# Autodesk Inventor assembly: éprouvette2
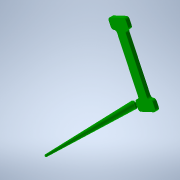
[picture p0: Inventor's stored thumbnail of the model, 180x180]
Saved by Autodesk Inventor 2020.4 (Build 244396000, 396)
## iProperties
Created: 2021-10
Part Number: éprouvette2
Document SubType Name: Assembly
Designer: mel
Author: mel
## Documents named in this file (6)
- D:\travail\année 2020-2021\itec\prépa injection plastique eduscol\dossier de travail\Ensemble des pièces de l'activité\Conception de moule1\éprouvette2.iam
- D:\travail\année 2020-2021\itec\prépa injection plastique eduscol\dossier de travail\Ensemble des pièces de l'activité\Conception de moule1\éprouvette2_éprouvette_LY.iam
- D:\travail\année 2020-2021\itec\prépa injection plastique eduscol\dossier de travail\Ensemble des pièces de l'activité\Conception de moule1\éprouvette2_RG.ipt
- D:\travail\année 2020-2021\itec\prépa injection plastique eduscol\dossier de travail\Ensemble des pièces de l'activité\Conception de moule1\Mo\FUTABA_SA-S 2\éprouvette2_MB.iam
- D:\travail\année 2020-2021\itec\prépa injection plastique eduscol\dossier de travail\Ensemble des pièces de l'activité\Conception de moule1\Buse d'injection\HASCO_Z51\éprouvette2_Z51-18x76-3,5.ipt
- D:\travail\année 2020-2021\itec\prépa injection plastique eduscol\dossier de travail\Ensemble des pièces de l'activité\Conception de moule1\Bague de centrage\LKM_LR\éprouvette2_LR-100-36.ipt
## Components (5 placed, 5 different names)
1. éprouvette2_éprouvette_LY:1 [sub-assembly] — Affleurement:1, Affleurement:2, Affleurement:3, Affleurement:10, Affleurement:11
2. éprouvette2_RG:1 — Affleurement:4, Affleurement:5, Affleurement:6, Affleurement:8, Placage:3
3. éprouvette2_MB:1 [sub-assembly] — Placage:1, Angle:1, Placage:2, Placage:4, Affleurement:11
4. éprouvette2_Z51-18x76-3,5:1 — Placage:2, Placage:3, Placage:5
5. éprouvette2_LR-100-36:1 — Placage:4, Placage:5
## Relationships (15: Flush 9, Mate 5, Angle 1)
- Affleurement:1 [Flush]: éprouvette2_éprouvette_LY:1
- Affleurement:2 [Flush]: éprouvette2_éprouvette_LY:1
- Affleurement:3 [Flush]: éprouvette2_éprouvette_LY:1
- Affleurement:4 [Flush]: éprouvette2_RG:1
- Affleurement:5 [Flush]: éprouvette2_RG:1
- Affleurement:6 [Flush]: éprouvette2_RG:1
- Affleurement:8 [Flush]: éprouvette2_RG:1
- Placage:1 [Mate]: éprouvette2_MB:1
- Angle:1: éprouvette2_MB:1
- Placage:2 [Mate]: éprouvette2_MB:1 ↔ éprouvette2_Z51-18x76-3,5:1
- Placage:3 [Mate]: éprouvette2_RG:1 ↔ éprouvette2_Z51-18x76-3,5:1
- Placage:4 [Mate]: éprouvette2_MB:1 ↔ éprouvette2_LR-100-36:1
- Placage:5 [Mate]: éprouvette2_Z51-18x76-3,5:1 ↔ éprouvette2_LR-100-36:1
- Affleurement:10 [Flush]: éprouvette2_éprouvette_LY:1
- Affleurement:11 [Flush]: éprouvette2_éprouvette_LY:1 ↔ éprouvette2_MB:1
